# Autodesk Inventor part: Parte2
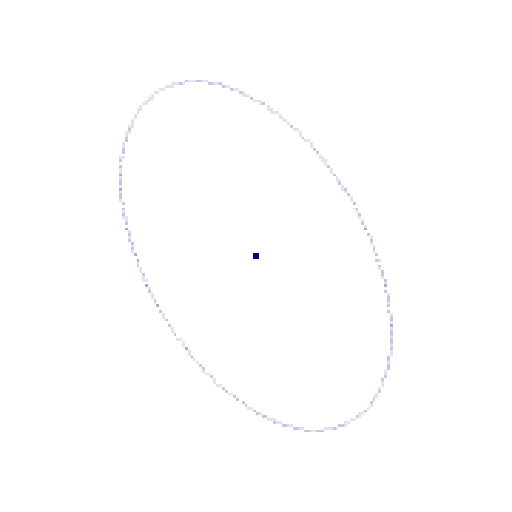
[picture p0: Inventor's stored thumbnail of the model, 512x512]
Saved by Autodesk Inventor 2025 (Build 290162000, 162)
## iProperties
Created: 2025-03
Part Number: Parte2
Material: Generico
Document SubType Name: Modeling
Designer: R5800u
Density: 1 g/cm^3
Appearance: Default
Author: R5800u
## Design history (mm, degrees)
sketch "Schizzo1"
  geometry: C1 r 108 at (0, 0); 1 further point
  constraints: 1 centre point, 1 coincident
  dimensions: "d0" = 216 dimension on point (0, 0) C1.centre C1; "d0" = 216 diameter of C1
